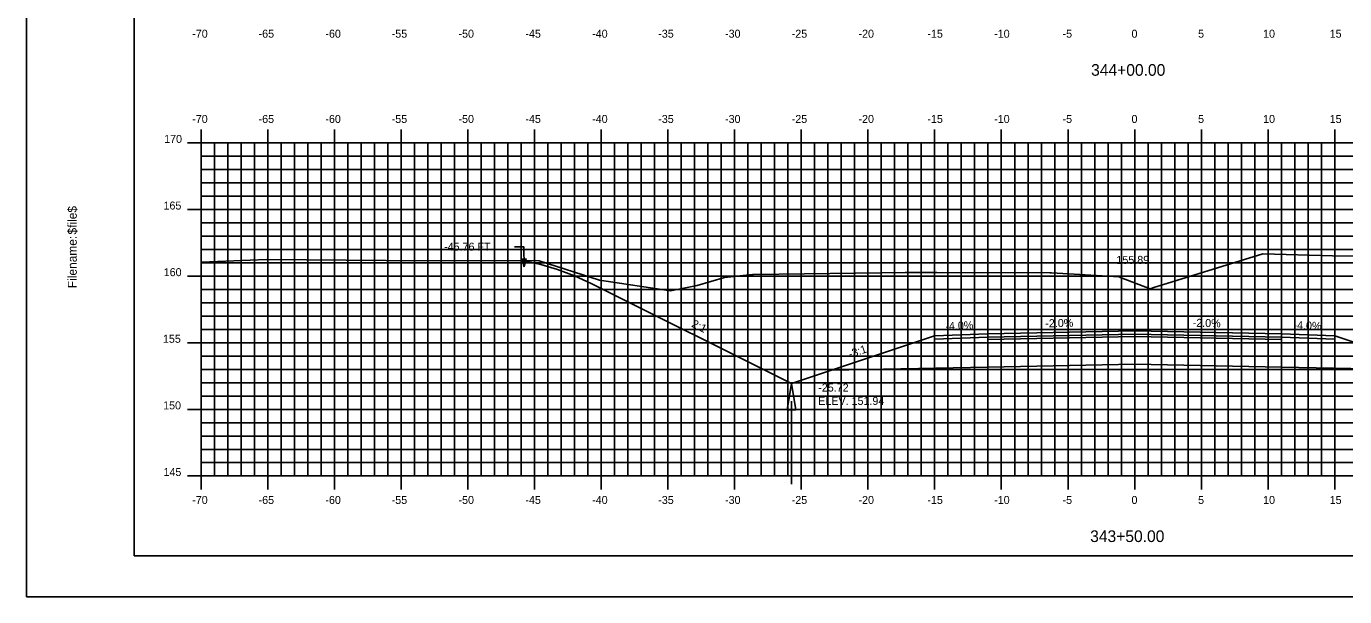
# Model space of a CAD drawing. Extents: x 1143420 to 1143590, y 608981 to 609091.
# Drawn here: x 1143420 to 1143518.8, y 608981.3 to 609024.1 of the extents above; entities that cross this region are included whole.
import ezdxf

# ---------------------------------------------------------------- set-up
doc = ezdxf.new("R2010")
doc.units = 0
for name, color, linetype in [('ANNOTATION', 7, 'Continuous'), ('BORDER', 7, 'Continuous'), ('D_Drainage_Ditch_Line', 7, 'Continuous'), ('D_Roadway_Centerline', 7, 'Continuous'), ('D_Roadway_Centerline_Text', 7, 'Continuous'), ('D_Roadway_Edge_Shoulder', 7, 'Continuous'), ('D_Roadway_Edge_TW', 7, 'Continuous'), ('D_Roadway_Pavement', 7, 'Continuous'), ('D_Roadway_SlopeLines', 7, 'Continuous'), ('D_Roadway_SubGrade', 7, 'Continuous'), ('D_Text_Standard', 7, 'Continuous'), ('H_V ANNOTATION', 7, 'Continuous'), ('MAJOR', 7, 'Continuous'), ('MINOR', 7, 'Continuous'), ('PLOT BOUNDARY', 7, 'Continuous'), ('S_Roadway_Centerline', 7, 'Continuous')]:
    doc.layers.add(name, color=color, linetype=linetype)

msp = doc.modelspace()

# ---------------------------------------------------------------- linework, layer by layer
msp.add_lwpolyline([(1143457.318, 609006.487), (1143458.568, 609006.213), (1143459.818, 609005.839), (1143461.068, 609005.365), (1143462.318, 609004.79), (1143477.355, 608997.271), (1143480.355, 608998.271), (1143488.079, 609000.846), (1143488.08, 609000.846), (1143492.08, 609001.006), (1143503.08, 609001.226), (1143514.08, 609001.006), (1143518.08, 609000.846), (1143525.803, 608998.271), (1143528.803, 608997.271), (1143545.139, 609005.439), (1143546.389, 609005.985), (1143547.639, 609006.372), (1143548.889, 609006.599), (1143550.139, 609006.669)])
at = {"layer": 'BORDER'}
msp.add_lwpolyline([(1143428.08, 608984.335), (1143588.08, 608984.335), (1143588.08, 609089.335), (1143428.08, 609089.335)], close=True, dxfattribs=at)
at = {"layer": 'D_Drainage_Ditch_Line'}
msp.add_line((1143477.355, 608995.959), (1143477.355, 608989.716), dxfattribs=at)
msp.add_lwpolyline([(1143477.683, 608995.303), (1143477.027, 608995.303), (1143477.355, 608997.271)], close=True, dxfattribs=at)
at = {"layer": 'D_Roadway_Edge_Shoulder'}
for points in [[(1143492.08, 609001.006), (1143488.08, 609000.846), (1143488.08, 609000.596), (1143492.08, 609000.756)], [(1143514.08, 609001.006), (1143518.08, 609000.846), (1143518.08, 609000.596), (1143514.08, 609000.756)]]:
    msp.add_lwpolyline(points, close=True, dxfattribs=at)
at = {"layer": 'D_Roadway_Edge_TW'}
msp.add_lwpolyline([(1143492.08, 609000.756), (1143492.08, 609001.006), (1143503.08, 609001.226), (1143514.08, 609001.006), (1143514.08, 609000.756), (1143503.08, 609000.976)], close=True, dxfattribs=at)
at = {"layer": 'D_Roadway_Pavement'}
msp.add_lwpolyline([(1143492.08, 609000.589), (1143492.08, 609000.756), (1143503.08, 609000.976), (1143514.08, 609000.756), (1143514.08, 609000.589), (1143503.08, 609000.809)], close=True, dxfattribs=at)
at = {"layer": 'D_Roadway_SlopeLines'}
for points in [[(1143477.355, 608997.271), (1143462.318, 609004.79), (1143461.068, 609005.365), (1143459.818, 609005.839), (1143458.568, 609006.213), (1143457.318, 609006.487)], [(1143480.355, 608998.271), (1143477.355, 608997.271)]]:
    msp.add_lwpolyline(points, dxfattribs=at)
at = {"layer": 'D_Roadway_SubGrade'}
for points in [[(1143492.08, 609000.589), (1143492.08, 609000.756), (1143488.08, 609000.596), (1143488.08, 609000.846), (1143488.079, 609000.846), (1143480.355, 608998.271), (1143492.08, 608998.506)], [(1143492.08, 608998.506), (1143492.08, 609000.589), (1143503.08, 609000.809), (1143514.08, 609000.589), (1143514.08, 608998.506), (1143503.08, 608998.726)], [(1143514.08, 609000.589), (1143514.08, 609000.756), (1143518.08, 609000.596), (1143518.08, 609000.846), (1143518.08, 609000.846), (1143525.803, 608998.271), (1143514.08, 608998.506)]]:
    msp.add_lwpolyline(points, close=True, dxfattribs=at)
at = {"layer": 'D_Text_Standard'}
msp.add_lwpolyline([(1143457.318, 609006.04), (1143457.27, 609007.546), (1143456.59, 609007.546)], dxfattribs=at)
msp.add_lwpolyline([(1143457.318, 609006.04), (1143457.154, 609006.617), (1143457.445, 609006.626)], close=True, dxfattribs=at)
at = {"layer": 'MAJOR'}
for p, q in [((1143433.08, 609016.337), (1143433.08, 609015.335)), ((1143438.08, 609016.337), (1143438.08, 609015.335)), ((1143443.08, 609016.337), (1143443.08, 609015.335)), ((1143448.08, 609016.337), (1143448.08, 609015.335)), ((1143453.08, 609016.337), (1143453.08, 609015.335)), ((1143458.08, 609016.337), (1143458.08, 609015.335)), ((1143463.08, 609016.337), (1143463.08, 609015.335)), ((1143468.08, 609016.337), (1143468.08, 609015.335)), ((1143473.08, 609016.337), (1143473.08, 609015.335)), ((1143478.08, 609016.337), (1143478.08, 609015.335)), ((1143483.08, 609016.337), (1143483.08, 609015.335)), ((1143488.08, 609016.337), (1143488.08, 609015.335)), ((1143493.08, 609016.337), (1143493.08, 609015.335)), ((1143498.08, 609016.337), (1143498.08, 609015.335)), ((1143503.08, 609016.337), (1143503.08, 609015.335)), ((1143508.08, 609016.337), (1143508.08, 609015.335)), ((1143513.08, 609016.337), (1143513.08, 609015.335)), ((1143518.08, 609016.337), (1143518.08, 609015.335)), ((1143432.078, 609015.335), (1143433.08, 609015.335)), ((1143433.08, 609015.335), (1143573.08, 609015.335)), ((1143433.08, 608990.335), (1143433.08, 609015.335)), ((1143433.08, 608990.335), (1143433.08, 609015.335)), ((1143433.08, 609015.335), (1143573.08, 609015.335)), ((1143438.08, 608990.335), (1143438.08, 609015.335)), ((1143443.08, 608990.335), (1143443.08, 609015.335)), ((1143448.08, 608990.335), (1143448.08, 609015.335)), ((1143453.08, 608990.335), (1143453.08, 609015.335)), ((1143458.08, 608990.335), (1143458.08, 609015.335)), ((1143463.08, 608990.335), (1143463.08, 609015.335)), ((1143468.08, 608990.335), (1143468.08, 609015.335)), ((1143473.08, 608990.335), (1143473.08, 609015.335)), ((1143478.08, 608990.335), (1143478.08, 609015.335)), ((1143483.08, 608990.335), (1143483.08, 609015.335)), ((1143488.08, 608990.335), (1143488.08, 609015.335)), ((1143493.08, 608990.335), (1143493.08, 609015.335)), ((1143498.08, 608990.335), (1143498.08, 609015.335)), ((1143503.08, 608990.335), (1143503.08, 609015.335)), ((1143508.08, 608990.335), (1143508.08, 609015.335)), ((1143513.08, 608990.335), (1143513.08, 609015.335)), ((1143518.08, 608990.335), (1143518.08, 609015.335)), ((1143432.078, 609010.335), (1143433.08, 609010.335)), ((1143433.08, 609010.335), (1143573.08, 609010.335)), ((1143432.078, 609005.335), (1143433.08, 609005.335)), ((1143433.08, 609005.335), (1143573.08, 609005.335)), ((1143432.078, 609000.335), (1143433.08, 609000.335)), ((1143433.08, 609000.335), (1143573.08, 609000.335)), ((1143432.078, 608995.335), (1143433.08, 608995.335)), ((1143433.08, 608995.335), (1143573.08, 608995.335)), ((1143432.078, 608990.335), (1143433.08, 608990.335)), ((1143433.08, 608990.335), (1143573.08, 608990.335)), ((1143433.08, 608990.335), (1143573.08, 608990.335)), ((1143433.08, 608989.333), (1143433.08, 608990.335)), ((1143438.08, 608989.333), (1143438.08, 608990.335)), ((1143443.08, 608989.333), (1143443.08, 608990.335)), ((1143448.08, 608989.333), (1143448.08, 608990.335)), ((1143453.08, 608989.333), (1143453.08, 608990.335)), ((1143458.08, 608989.333), (1143458.08, 608990.335)), ((1143463.08, 608989.333), (1143463.08, 608990.335)), ((1143468.08, 608989.333), (1143468.08, 608990.335)), ((1143473.08, 608989.333), (1143473.08, 608990.335)), ((1143478.08, 608989.333), (1143478.08, 608990.335)), ((1143483.08, 608989.333), (1143483.08, 608990.335)), ((1143488.08, 608989.333), (1143488.08, 608990.335)), ((1143493.08, 608989.333), (1143493.08, 608990.335)), ((1143498.08, 608989.333), (1143498.08, 608990.335)), ((1143503.08, 608989.333), (1143503.08, 608990.335)), ((1143508.08, 608989.333), (1143508.08, 608990.335)), ((1143513.08, 608989.333), (1143513.08, 608990.335)), ((1143518.08, 608989.333), (1143518.08, 608990.335))]:
    msp.add_line(p, q, dxfattribs=at)
at = {"layer": 'MINOR'}
for p, q in [((1143434.08, 608990.335), (1143434.08, 609015.335)), ((1143435.08, 608990.335), (1143435.08, 609015.335)), ((1143436.08, 608990.335), (1143436.08, 609015.335)), ((1143437.08, 608990.335), (1143437.08, 609015.335)), ((1143439.08, 608990.335), (1143439.08, 609015.335)), ((1143440.08, 608990.335), (1143440.08, 609015.335)), ((1143441.08, 608990.335), (1143441.08, 609015.335)), ((1143442.08, 608990.335), (1143442.08, 609015.335)), ((1143444.08, 608990.335), (1143444.08, 609015.335)), ((1143445.08, 608990.335), (1143445.08, 609015.335)), ((1143446.08, 608990.335), (1143446.08, 609015.335)), ((1143447.08, 608990.335), (1143447.08, 609015.335)), ((1143449.08, 608990.335), (1143449.08, 609015.335)), ((1143450.08, 608990.335), (1143450.08, 609015.335)), ((1143451.08, 608990.335), (1143451.08, 609015.335)), ((1143452.08, 608990.335), (1143452.08, 609015.335)), ((1143454.08, 608990.335), (1143454.08, 609015.335)), ((1143455.08, 608990.335), (1143455.08, 609015.335)), ((1143456.08, 608990.335), (1143456.08, 609015.335)), ((1143457.08, 608990.335), (1143457.08, 609015.335)), ((1143459.08, 608990.335), (1143459.08, 609015.335)), ((1143460.08, 608990.335), (1143460.08, 609015.335)), ((1143461.08, 608990.335), (1143461.08, 609015.335)), ((1143462.08, 608990.335), (1143462.08, 609015.335)), ((1143464.08, 608990.335), (1143464.08, 609015.335)), ((1143465.08, 608990.335), (1143465.08, 609015.335)), ((1143466.08, 608990.335), (1143466.08, 609015.335)), ((1143467.08, 608990.335), (1143467.08, 609015.335)), ((1143469.08, 608990.335), (1143469.08, 609015.335)), ((1143470.08, 608990.335), (1143470.08, 609015.335)), ((1143471.08, 608990.335), (1143471.08, 609015.335)), ((1143472.08, 608990.335), (1143472.08, 609015.335)), ((1143474.08, 608990.335), (1143474.08, 609015.335)), ((1143475.08, 608990.335), (1143475.08, 609015.335)), ((1143476.08, 608990.335), (1143476.08, 609015.335)), ((1143477.08, 608990.335), (1143477.08, 609015.335)), ((1143479.08, 608990.335), (1143479.08, 609015.335)), ((1143480.08, 608990.335), (1143480.08, 609015.335)), ((1143481.08, 608990.335), (1143481.08, 609015.335)), ((1143482.08, 608990.335), (1143482.08, 609015.335)), ((1143484.08, 608990.335), (1143484.08, 609015.335)), ((1143485.08, 608990.335), (1143485.08, 609015.335)), ((1143486.08, 608990.335), (1143486.08, 609015.335)), ((1143487.08, 608990.335), (1143487.08, 609015.335)), ((1143489.08, 608990.335), (1143489.08, 609015.335)), ((1143490.08, 608990.335), (1143490.08, 609015.335)), ((1143491.08, 608990.335), (1143491.08, 609015.335)), ((1143492.08, 608990.335), (1143492.08, 609015.335)), ((1143494.08, 608990.335), (1143494.08, 609015.335)), ((1143495.08, 608990.335), (1143495.08, 609015.335)), ((1143496.08, 608990.335), (1143496.08, 609015.335)), ((1143497.08, 608990.335), (1143497.08, 609015.335)), ((1143499.08, 608990.335), (1143499.08, 609015.335)), ((1143500.08, 608990.335), (1143500.08, 609015.335)), ((1143501.08, 608990.335), (1143501.08, 609015.335)), ((1143502.08, 608990.335), (1143502.08, 609015.335)), ((1143504.08, 608990.335), (1143504.08, 609015.335)), ((1143505.08, 608990.335), (1143505.08, 609015.335)), ((1143506.08, 608990.335), (1143506.08, 609015.335)), ((1143507.08, 608990.335), (1143507.08, 609015.335)), ((1143509.08, 608990.335), (1143509.08, 609015.335)), ((1143510.08, 608990.335), (1143510.08, 609015.335)), ((1143511.08, 608990.335), (1143511.08, 609015.335)), ((1143512.08, 608990.335), (1143512.08, 609015.335)), ((1143514.08, 608990.335), (1143514.08, 609015.335)), ((1143515.08, 608990.335), (1143515.08, 609015.335)), ((1143516.08, 608990.335), (1143516.08, 609015.335)), ((1143517.08, 608990.335), (1143517.08, 609015.335)), ((1143433.08, 609014.335), (1143573.08, 609014.335)), ((1143433.08, 609014.335), (1143434.082, 609014.335)), ((1143433.08, 609013.335), (1143573.08, 609013.335)), ((1143433.08, 609013.335), (1143434.082, 609013.335)), ((1143433.08, 609012.335), (1143573.08, 609012.335)), ((1143433.08, 609012.335), (1143434.082, 609012.335)), ((1143433.08, 609011.335), (1143573.08, 609011.335)), ((1143433.08, 609011.335), (1143434.082, 609011.335)), ((1143433.08, 609009.335), (1143573.08, 609009.335)), ((1143433.08, 609009.335), (1143434.082, 609009.335)), ((1143433.08, 609008.335), (1143573.08, 609008.335)), ((1143433.08, 609008.335), (1143434.082, 609008.335)), ((1143433.08, 609007.335), (1143573.08, 609007.335)), ((1143433.08, 609007.335), (1143434.082, 609007.335)), ((1143433.08, 609006.335), (1143573.08, 609006.335)), ((1143433.08, 609006.335), (1143434.082, 609006.335)), ((1143433.08, 609004.335), (1143573.08, 609004.335)), ((1143433.08, 609004.335), (1143434.082, 609004.335)), ((1143433.08, 609003.335), (1143573.08, 609003.335)), ((1143433.08, 609003.335), (1143434.082, 609003.335)), ((1143433.08, 609002.335), (1143573.08, 609002.335)), ((1143433.08, 609002.335), (1143434.082, 609002.335)), ((1143433.08, 609001.335), (1143573.08, 609001.335)), ((1143433.08, 609001.335), (1143434.082, 609001.335)), ((1143433.08, 608999.335), (1143573.08, 608999.335)), ((1143433.08, 608999.335), (1143434.082, 608999.335)), ((1143433.08, 608998.335), (1143573.08, 608998.335)), ((1143433.08, 608998.335), (1143434.082, 608998.335)), ((1143433.08, 608997.335), (1143573.08, 608997.335)), ((1143433.08, 608997.335), (1143434.082, 608997.335)), ((1143433.08, 608996.335), (1143573.08, 608996.335)), ((1143433.08, 608996.335), (1143434.082, 608996.335)), ((1143433.08, 608994.335), (1143573.08, 608994.335)), ((1143433.08, 608994.335), (1143434.082, 608994.335)), ((1143433.08, 608993.335), (1143573.08, 608993.335)), ((1143433.08, 608993.335), (1143434.082, 608993.335)), ((1143433.08, 608992.335), (1143573.08, 608992.335)), ((1143433.08, 608992.335), (1143434.082, 608992.335)), ((1143433.08, 608991.335), (1143573.08, 608991.335)), ((1143433.08, 608991.335), (1143434.082, 608991.335))]:
    msp.add_line(p, q, dxfattribs=at)
at = {"layer": 'PLOT BOUNDARY'}
msp.add_lwpolyline([(1143419.986, 608981.276), (1143589.986, 608981.276), (1143589.986, 609091.276), (1143419.986, 609091.276)], close=True, dxfattribs=at)
at = {"layer": 'S_Roadway_Centerline'}
msp.add_lwpolyline([(1143433.08, 609006.398), (1143437.983, 609006.589), (1143446.959, 609006.499), (1143458.437, 609006.485), (1143462.967, 609005.025), (1143468.267, 609004.229), (1143470.266, 609004.634), (1143472.319, 609005.24), (1143474.432, 609005.454), (1143474.512, 609005.456), (1143482.15, 609005.563), (1143485.877, 609005.61), (1143488.245, 609005.61), (1143496.712, 609005.592), (1143496.838, 609005.583), (1143501.911, 609005.274), (1143502.012, 609005.24), (1143504.24, 609004.385), (1143504.505, 609004.496), (1143512.688, 609007.008), (1143517.913, 609006.865), (1143539.07, 609006.733), (1143540.761, 609006.746), (1143573.08, 609006.481)], dxfattribs=at)

# ---------------------------------------------------------------- texts
at = {"layer": 'ANNOTATION'}
for s, rotation, p in [('2:1', 333.43495, (1143469.803, 609001.565)), ('-4.0%', 2.29061, (1143488.896, 609001.279)), ('-2.0%', 1.14576, (1143496.383, 609001.492)), ('-2.0%', 358.85424, (1143507.423, 609001.539)), ('-4.0%', 357.70939, (1143514.975, 609001.371)), ('-3:1', 18.43482, (1143481.734, 608999.185))]:
    msp.add_text(s, height=0.6, rotation=rotation, dxfattribs=at).set_placement(p)
at = {"layer": 'BORDER'}
for s, p in [('$file$', (1143423.765, 609008.461)), ('Filename:', (1143423.765, 609004.433))]:
    msp.add_text(s, height=0.6696, rotation=90, dxfattribs=at).set_placement(p)
at = {"layer": 'D_Roadway_Centerline'}
for s, p in [('C', (1143503.074, 609001.226)), ('L', (1143503.08, 609001.219))]:
    msp.add_text(s, height=0.0146, dxfattribs=at).set_placement(p)
at = {"layer": 'D_Roadway_Centerline_Text'}
msp.add_text('155.89', height=0.6, dxfattribs=at).set_placement((1143501.71, 609006.258))
at = {"layer": 'D_Text_Standard'}
for s, p in [('-45.76 FT', (1143451.307, 609007.246)), ('-25.72', (1143479.355, 608996.671)), ('ELEV. 151.94', (1143479.355, 608995.669))]:
    msp.add_text(s, height=0.6, dxfattribs=at).set_placement(p)
at = {"layer": 'H_V ANNOTATION'}
for s, height, p in [('-70', 0.6, (1143432.421, 609023.235)), ('-65', 0.6, (1143437.397, 609023.235)), ('-60', 0.6, (1143442.405, 609023.235)), ('-55', 0.6, (1143447.376, 609023.235)), ('-50', 0.6, (1143452.384, 609023.235)), ('-45', 0.6, (1143457.397, 609023.235)), ('-40', 0.6, (1143462.405, 609023.235)), ('-35', 0.6, (1143467.36, 609023.235)), ('-30', 0.6, (1143472.368, 609023.235)), ('-25', 0.6, (1143477.365, 609023.235)), ('-20', 0.6, (1143482.373, 609023.235)), ('-15', 0.6, (1143487.536, 609023.235)), ('-10', 0.6, (1143492.544, 609023.235)), ('-5', 0.6, (1143497.67, 609023.235)), ('0', 0.6, (1143502.839, 609023.235)), ('5', 0.6, (1143507.831, 609023.235)), ('10', 0.6, (1143512.705, 609023.235)), ('15', 0.6, (1143517.697, 609023.235)), ('344+00.00', 0.875, (1143499.81, 609020.378)), ('-70', 0.6, (1143432.421, 609016.835)), ('-65', 0.6, (1143437.397, 609016.835)), ('-60', 0.6, (1143442.405, 609016.835)), ('-55', 0.6, (1143447.376, 609016.835)), ('-50', 0.6, (1143452.384, 609016.835)), ('-45', 0.6, (1143457.397, 609016.835)), ('-40', 0.6, (1143462.405, 609016.835)), ('-35', 0.6, (1143467.36, 609016.835)), ('-30', 0.6, (1143472.368, 609016.835)), ('-25', 0.6, (1143477.365, 609016.835)), ('-20', 0.6, (1143482.373, 609016.835)), ('-15', 0.6, (1143487.536, 609016.835)), ('-10', 0.6, (1143492.544, 609016.835)), ('-5', 0.6, (1143497.67, 609016.835)), ('0', 0.6, (1143502.839, 609016.835)), ('5', 0.6, (1143507.831, 609016.835)), ('10', 0.6, (1143512.705, 609016.835)), ('15', 0.6, (1143517.697, 609016.835)), ('170', 0.6, (1143430.316, 609015.335)), ('165', 0.6, (1143430.268, 609010.335)), ('160', 0.6, (1143430.284, 609005.335)), ('155', 0.6, (1143430.225, 609000.335)), ('150', 0.6, (1143430.241, 608995.335)), ('145', 0.6, (1143430.268, 608990.335)), ('-70', 0.6, (1143432.421, 608988.235)), ('-65', 0.6, (1143437.397, 608988.235)), ('-60', 0.6, (1143442.405, 608988.235)), ('-55', 0.6, (1143447.376, 608988.235)), ('-50', 0.6, (1143452.384, 608988.235)), ('-45', 0.6, (1143457.397, 608988.235)), ('-40', 0.6, (1143462.405, 608988.235)), ('-35', 0.6, (1143467.36, 608988.235)), ('-30', 0.6, (1143472.368, 608988.235)), ('-25', 0.6, (1143477.365, 608988.235)), ('-20', 0.6, (1143482.373, 608988.235)), ('-15', 0.6, (1143487.536, 608988.235)), ('-10', 0.6, (1143492.544, 608988.235)), ('-5', 0.6, (1143497.67, 608988.235)), ('0', 0.6, (1143502.839, 608988.235)), ('5', 0.6, (1143507.831, 608988.235)), ('10', 0.6, (1143512.705, 608988.235)), ('15', 0.6, (1143517.697, 608988.235)), ('343+50.00', 0.875, (1143499.74, 608985.378))]:
    msp.add_text(s, height=height, dxfattribs=at).set_placement(p)
at = {"layer": 'MAJOR'}
msp.add_text('-', height=0.006, dxfattribs=at).set_placement((1143433.075, 608990.335))
at = {"layer": 'S_Roadway_Centerline'}
for s, p in [('L', (1143485.869, 609005.603)), ('C', (1143485.872, 609005.61))]:
    msp.add_text(s, height=0.0146, dxfattribs=at).set_placement(p)

doc.saveas('drawing.dxf')
